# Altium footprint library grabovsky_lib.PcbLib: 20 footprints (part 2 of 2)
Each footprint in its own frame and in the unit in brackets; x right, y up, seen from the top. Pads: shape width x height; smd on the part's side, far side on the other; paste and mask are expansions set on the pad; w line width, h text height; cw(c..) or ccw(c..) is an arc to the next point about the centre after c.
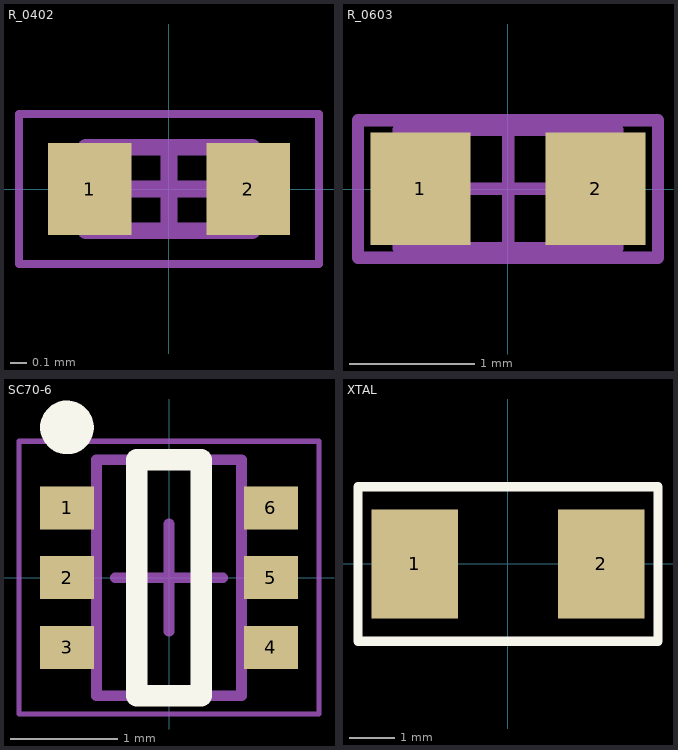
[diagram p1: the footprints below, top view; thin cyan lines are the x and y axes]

## R_0402 [mm]
height 2
pads (2):
  rect 0.5x0.55 smd: 1(-0.475,0) 2(0.475,0)
Mechanical 13:
  lines w0.1: -0.5,-0.25 -0.5,0.25 0.5,0.25 0.5,-0.25 -0.5,-0.25
Mechanical 15:
  lines w0.05: -0.9,-0.45 -0.9,0.45 0.9,0.45 0.9,-0.45 -0.9,-0.45
  lines w0.1: -0.25,0 0.25,0 ; 0,-0.25 0,0.25
3D body "RES0402.stp": height 0.3, standoff 0, extent -0.5,-0.25 0.5,0.25

## R_0603 [mm]
pads (2):
  rect 0.8x0.9 smd: 1(-0.7,0) 2(0.7,0)
Mechanical 13:
  lines w0.1: -0.875,-0.475 -0.875,0.475 0.875,0.475 0.875,-0.475 -0.875,-0.475
Mechanical 15:
  lines w0.1: -0.475,0 0.475,0 ; 0,-0.475 0,0.475 ; -1.2,-0.55 -1.2,0.55 1.2,0.55 1.2,-0.55 -1.2,-0.55
3D body "res0603r.STEP": height 0.45, standoff 0, extent -0.8,-0.4 0.8,0.4

## SC70-6 [mm]
pads (6):
  rect 0.5x0.4 smd: 1(-0.95,0.65) 2(-0.95,0) 3(-0.95,-0.65) 4(0.95,-0.65) 5(0.95,0) 6(0.95,0.65)
Top Overlay:
  circle w0.25: c-0.95,1.4 r0.125
  lines w0.2: -0.3,-1.1 0.3,-1.1 0.3,1.1 -0.3,1.1 -0.3,-1.1
Mechanical 13:
  lines w0.1: -0.675,-1.1 -0.675,1.1 0.675,1.1 0.675,-1.1 -0.675,-1.1
Mechanical 15:
  lines w0.05: -1.397,-1.27 -1.397,1.27 1.397,1.27 1.397,-1.27 -1.397,-1.27
  lines w0.1: -0.5,0 0.5,0 ; 0,-0.5 0,0.5
3D body "SOT23127P600-8N.step": height 1.1, standoff 0, extent -1.2,-1.1 1.2,1.1

## XTAL [mm]
pads (2):
  rect 1.9x2.4 smd: 1(-2.05,0) 2(2.05,0)
Top Overlay:
  lines w0.2: -3.302,-1.7 3.302,-1.7 3.302,1.7 -0.2,1.7 -3.302,1.7 -3.302,0.848 -3.302,-1.7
